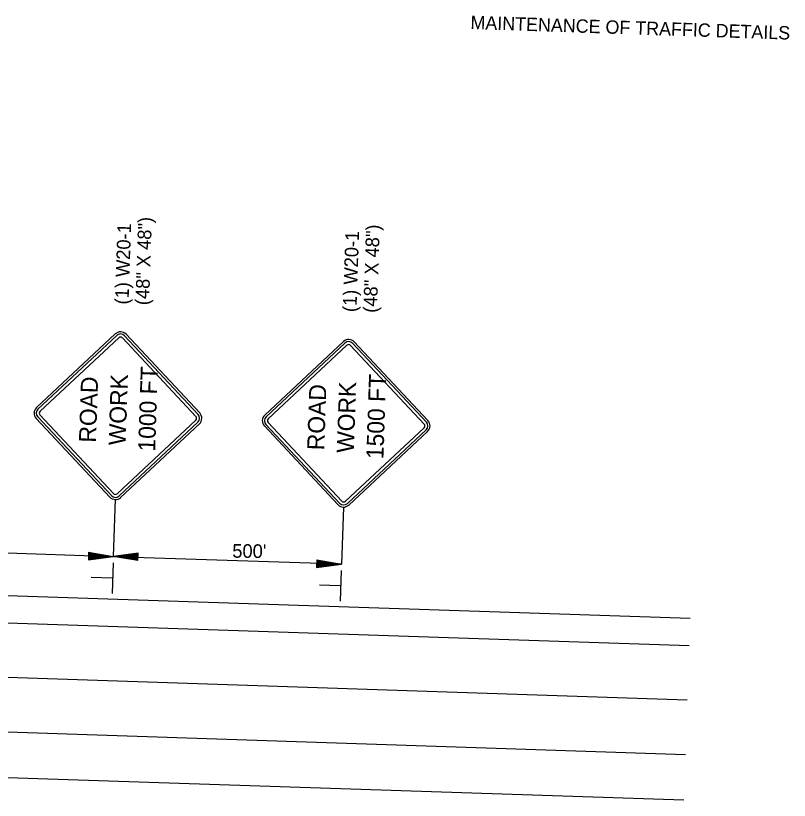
# Model space of a CAD drawing. Extents: x 977269 to 979191, y 1525946 to 1526973.
# Drawn here: x 978434.9 to 978774.1, y 1526587.6 to 1526931.8 of the extents above; entities that cross this region are included whole.
import ezdxf

# ---------------------------------------------------------------- set-up
doc = ezdxf.new("R2010")
doc.units = 0
for name, color, linetype in [('R_Border', 7, 'Continuous'), ('R_Border Prem', 7, 'Continuous'), ('STAMP', 7, 'Continuous'), ('STAMP_PP', 7, 'Continuous')]:
    doc.layers.add(name, color=color, linetype=linetype)

msp = doc.modelspace()

# ---------------------------------------------------------------- linework, layer by layer
at = {"layer": 'STAMP'}
for p, q in [((978478.51, 1526719.59), (978477.68, 1526694.6)), ((978578.58, 1526716.25), (978577.75, 1526691.27)), ((978377.74, 1526697.94), (978477.68, 1526694.6)), ((978466.83, 1526696.42), (978466.77, 1526693.16)), ((978466.79, 1526694.26), (978470.34, 1526694.73)), ((978466.8, 1526695.05), (978468.52, 1526694.76)), ((978466.8, 1526694.53), (978468.52, 1526694.76)), ((978466.81, 1526695.32), (978470.34, 1526694.73)), ((978466.82, 1526695.87), (978473.99, 1526694.67)), ((978466.82, 1526695.6), (978472.18, 1526694.7)), ((978466.83, 1526696.42), (978477.68, 1526694.6)), ((978466.83, 1526696.15), (978475.86, 1526694.63)), ((978488.59, 1526696.05), (978477.68, 1526694.6)), ((978488.58, 1526695.78), (978479.5, 1526694.57)), ((978488.58, 1526695.5), (978481.37, 1526694.54)), ((978488.57, 1526695.23), (978483.18, 1526694.51)), ((978488.57, 1526694.95), (978485.02, 1526694.48)), ((978488.53, 1526692.78), (978488.59, 1526696.05)), ((978466.77, 1526693.16), (978477.68, 1526694.6)), ((978466.78, 1526693.71), (978473.99, 1526694.67)), ((978466.78, 1526693.43), (978475.86, 1526694.63)), ((978466.79, 1526693.98), (978472.18, 1526694.7)), ((978477.58, 1526691.74), (978477.14, 1526678.28)), ((978477.68, 1526694.6), (978577.63, 1526691.3)), ((978488.53, 1526692.78), (978477.68, 1526694.6)), ((978488.53, 1526693.06), (978479.5, 1526694.57)), ((978488.54, 1526693.33), (978481.37, 1526694.54)), ((978488.54, 1526693.61), (978483.18, 1526694.51)), ((978488.55, 1526693.89), (978485.02, 1526694.48)), ((978488.56, 1526694.67), (978486.84, 1526694.45)), ((978488.55, 1526694.16), (978486.84, 1526694.45)), ((978566.9, 1526693.08), (978566.84, 1526689.82)), ((978566.84, 1526690.1), (978575.93, 1526691.29)), ((978566.85, 1526690.64), (978572.25, 1526691.36)), ((978566.85, 1526690.37), (978574.06, 1526691.33)), ((978566.86, 1526691.2), (978568.58, 1526691.42)), ((978566.86, 1526690.92), (978570.4, 1526691.39)), ((978566.87, 1526691.71), (978568.58, 1526691.42)), ((978566.88, 1526692.26), (978572.25, 1526691.36)), ((978566.88, 1526691.98), (978570.4, 1526691.39)), ((978566.89, 1526692.82), (978575.93, 1526691.29)), ((978566.89, 1526692.54), (978574.06, 1526691.33)), ((978566.9, 1526693.08), (978577.75, 1526691.27)), ((978566.84, 1526689.82), (978577.75, 1526691.27)), ((978577.65, 1526688.4), (978577.2, 1526674.94)), ((978477.17, 1526685.04), (978467.98, 1526685.35)), ((978730.57, 1526667.37), (978296.8, 1526681.84)), ((978577.23, 1526681.71), (978568.05, 1526682.01)), ((978730.17, 1526655.41), (978296.4, 1526669.87)), ((978729.37, 1526631.48), (978295.6, 1526645.95)), ((978728.57, 1526607.56), (978294.8, 1526622.02)), ((978727.91, 1526587.62), (978294.14, 1526602.09))]:
    msp.add_line(p, q, dxfattribs=at)
at = {"layer": 'STAMP_PP'}
for p, q in [((978444.04, 1526759.93), (978478.55, 1526792.21)), ((978444.68, 1526759.25), (978479.19, 1526791.53)), ((978482.63, 1526791.41), (978514.91, 1526756.91)), ((978483.32, 1526792.05), (978515.6, 1526757.55)), ((978445.58, 1526758.29), (978480.08, 1526790.57)), ((978481.67, 1526790.52), (978513.95, 1526756.01)), ((978544.11, 1526756.6), (978578.61, 1526788.88)), ((978544.75, 1526755.91), (978579.25, 1526788.19)), ((978582.7, 1526788.08), (978614.98, 1526753.57)), ((978583.38, 1526788.72), (978615.66, 1526754.21)), ((978545.65, 1526754.95), (978580.15, 1526787.23)), ((978581.74, 1526787.18), (978614.02, 1526752.67)), ((978477.8, 1526722.19), (978445.53, 1526756.7)), ((978476.16, 1526720.66), (978443.88, 1526755.16)), ((978476.85, 1526721.3), (978444.57, 1526755.8)), ((978513.9, 1526754.42), (978479.39, 1526722.14)), ((978514.8, 1526753.46), (978480.29, 1526721.18)), ((978577.87, 1526718.86), (978545.59, 1526753.36)), ((978515.44, 1526752.78), (978480.93, 1526720.5)), ((978576.23, 1526717.32), (978543.95, 1526751.83)), ((978576.91, 1526717.96), (978544.63, 1526752.47)), ((978613.97, 1526751.08), (978579.46, 1526718.81)), ((978614.86, 1526750.13), (978580.36, 1526717.85)), ((978615.5, 1526749.44), (978581, 1526717.16))]:
    msp.add_line(p, q, dxfattribs=at)
for centre, radius, start, end in [((978480.85, 1526789.75), 3.37, 43.0901, 133.0901), ((978480.85, 1526789.75), 2.44, 43.0901, 133.0901), ((978480.85, 1526789.75), 1.12, 43.0901, 133.0901), ((978580.92, 1526786.41), 3.37, 43.0901, 133.0901), ((978580.92, 1526786.41), 2.44, 43.0901, 133.0901), ((978580.92, 1526786.41), 1.12, 43.0901, 133.0901), ((978446.35, 1526757.47), 3.38, 133.0901, 223.0901), ((978446.35, 1526757.47), 2.44, 133.0901, 223.0901), ((978446.35, 1526757.47), 1.13, 133.0901, 223.0901), ((978513.13, 1526755.24), 2.44, 313.0901, 43.0901), ((978513.13, 1526755.24), 3.38, 313.0901, 43.0901), ((978513.13, 1526755.24), 1.13, 313.0901, 43.0901), ((978546.41, 1526754.13), 3.38, 133.0901, 223.0901), ((978546.41, 1526754.13), 2.44, 133.0901, 223.0901), ((978546.41, 1526754.13), 1.13, 133.0901, 223.0901), ((978613.2, 1526751.91), 2.44, 313.0901, 43.0901), ((978613.2, 1526751.91), 3.38, 313.0901, 43.0901), ((978613.2, 1526751.91), 1.13, 313.0901, 43.0901), ((978478.63, 1526722.96), 3.38, 223.0901, 313.0901), ((978478.63, 1526722.96), 2.44, 223.0901, 313.0901), ((978478.63, 1526722.96), 1.12, 223.0901, 313.0901), ((978578.69, 1526719.63), 1.12, 223.0901, 313.0901), ((978578.69, 1526719.63), 3.38, 223.0901, 313.0901), ((978578.69, 1526719.63), 2.44, 223.0901, 313.0901)]:
    msp.add_arc(centre, radius, start, end, dxfattribs=at)

# ---------------------------------------------------------------- texts
at = {"layer": 'R_Border'}
for s, p in [('(48" X 48")', (978493.36, 1526804.76)), ('(1) W20-1', (978484.37, 1526805.06)), ('(48" X 48")', (978593.3, 1526801.43)), ('(1) W20-1', (978584.31, 1526801.73))]:
    msp.add_text(s, height=6, rotation=88.0901, dxfattribs=at).set_placement(p)
at = {"layer": 'R_Border Prem'}
msp.add_text('MAINTENANCE OF TRAFFIC DETAILS', height=5.862, rotation=358.0901, dxfattribs=at).set_placement((978634.24, 1526925.99))
at = {"layer": 'STAMP'}
msp.add_text("500'", height=6, rotation=359.3204, dxfattribs=at).set_placement((978529.85, 1526694.06))
at = {"layer": 'STAMP_PP'}
for s, p in [('1000 FT', (978496.05, 1526740.51)), ('WORK', (978483.11, 1526743.24)), ('1500 FT', (978596.12, 1526737.18)), (' ROAD ', (978470.03, 1526741.65)), ('WORK', (978583.18, 1526739.91)), (' ROAD ', (978570.1, 1526738.31))]:
    msp.add_text(s, height=7.5, rotation=88.0901, dxfattribs=at).set_placement(p)

doc.saveas('drawing.dxf')
